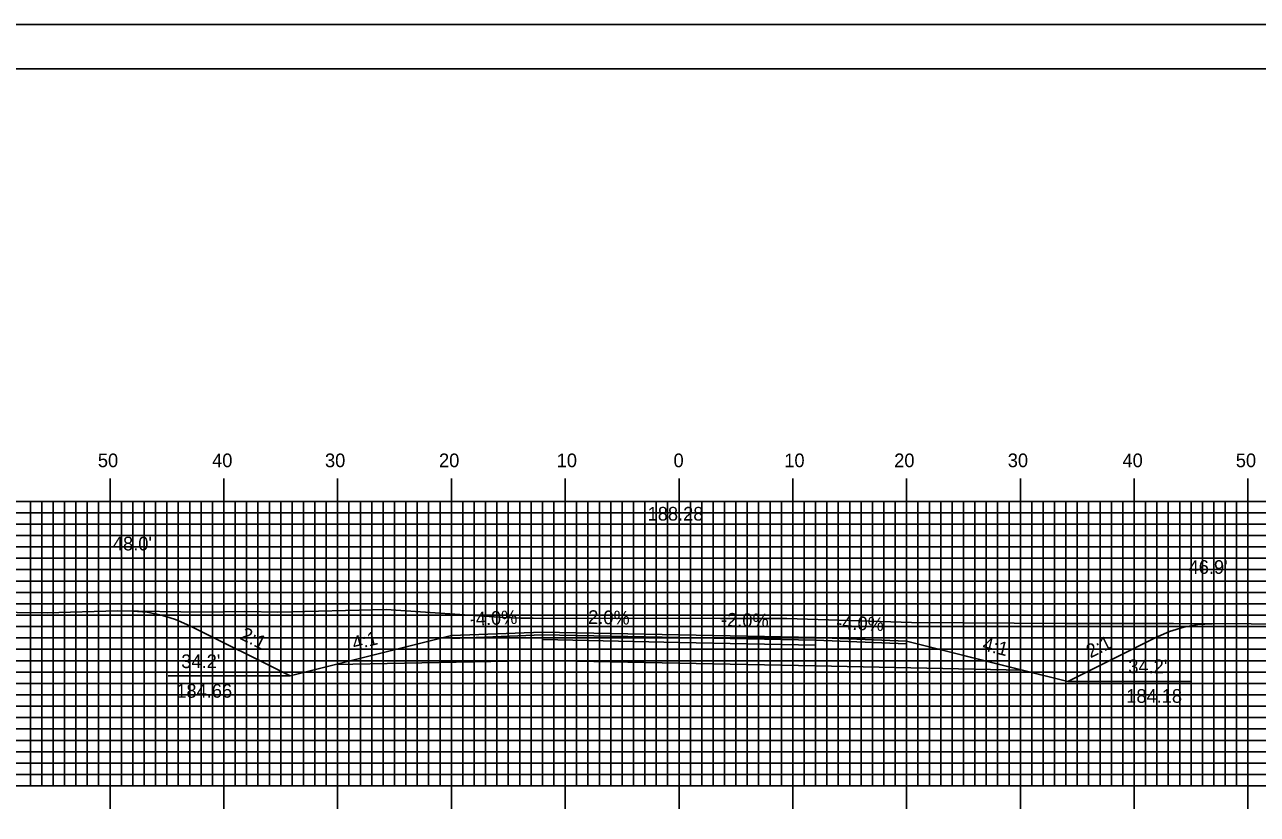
# Model space of a CAD drawing. Extents: x 1797994 to 1798337, y 442591 to 442811.
# Drawn here: x 1798102.5 to 1798210.8, y 442741.2 to 442810.5 of the extents above; entities that cross this region are included whole.
import ezdxf

# ---------------------------------------------------------------- set-up
doc = ezdxf.new("R2010")
doc.units = 0
for name, color, linetype in [('ANNOTATION', 7, 'Continuous'), ('BORDER', 7, 'Continuous'), ('D_Roadway_Centerline', 7, 'Continuous'), ('D_Roadway_Centerline_Text', 7, 'Continuous'), ('D_Roadway_Edge_Shoulder', 7, 'Continuous'), ('D_Roadway_Edge_TW', 7, 'Continuous'), ('D_Roadway_Pavement', 7, 'Continuous'), ('D_Roadway_SlopeLines', 7, 'Continuous'), ('D_Roadway_SubGrade', 7, 'Continuous'), ('D_Text_Standard', 7, 'Continuous'), ('H_V ANNOTATION', 7, 'Continuous'), ('MAJOR', 7, 'Continuous'), ('MINOR', 7, 'Continuous'), ('PDRAIN', 7, 'Continuous'), ('PLOT BOUNDARY', 7, 'Continuous'), ('S_Roadway_Centerline', 7, 'Continuous')]:
    doc.layers.add(name, color=color, linetype=linetype)

msp = doc.modelspace()

# ---------------------------------------------------------------- linework, layer by layer
at = {"layer": 'BORDER'}
msp.add_lwpolyline([(1798010.36, 442596.67), (1798330.36, 442596.67), (1798330.36, 442806.67), (1798010.36, 442806.67)], close=True, dxfattribs=at)
at = {"layer": 'D_Roadway_Centerline'}
msp.add_lwpolyline([(1798111.97, 442759.03), (1798113.22, 442758.93), (1798114.47, 442758.68), (1798115.72, 442758.28), (1798116.97, 442757.73), (1798125.78, 442753.33), (1798129.78, 442754.33), (1798139.96, 442756.87), (1798147.96, 442757.19), (1798159.96, 442756.95), (1798171.96, 442756.71), (1798179.96, 442756.39), (1798190.13, 442753.85), (1798194.13, 442752.85), (1798201.81, 442756.69), (1798203.06, 442757.23), (1798204.31, 442757.62), (1798205.56, 442757.85), (1798206.81, 442757.92)], dxfattribs=at)
at = {"layer": 'D_Roadway_Edge_Shoulder'}
for points in [[(1798147.96, 442757.19), (1798139.96, 442756.87), (1798139.96, 442756.62), (1798147.96, 442756.94)], [(1798171.96, 442756.71), (1798179.96, 442756.39), (1798179.96, 442756.14), (1798171.96, 442756.46)]]:
    msp.add_lwpolyline(points, close=True, dxfattribs=at)
at = {"layer": 'D_Roadway_Edge_TW'}
msp.add_lwpolyline([(1798147.96, 442756.94), (1798147.96, 442757.19), (1798159.96, 442756.95), (1798171.96, 442756.71), (1798171.96, 442756.46), (1798159.96, 442756.7)], close=True, dxfattribs=at)
at = {"layer": 'D_Roadway_Pavement'}
msp.add_lwpolyline([(1798147.96, 442756.52), (1798147.96, 442756.94), (1798159.96, 442756.7), (1798171.96, 442756.46), (1798171.96, 442756.04), (1798159.96, 442756.28)], close=True, dxfattribs=at)
at = {"layer": 'D_Roadway_SlopeLines'}
for points in [[(1798125.78, 442753.33), (1798116.97, 442757.73), (1798115.72, 442758.28), (1798114.47, 442758.68), (1798113.22, 442758.93), (1798111.97, 442759.03)], [(1798194.13, 442752.85), (1798201.81, 442756.69), (1798203.06, 442757.23), (1798204.31, 442757.62), (1798205.56, 442757.85), (1798206.81, 442757.92)], [(1798139.96, 442756.87), (1798125.78, 442753.33)], [(1798179.96, 442756.39), (1798194.13, 442752.85)]]:
    msp.add_lwpolyline(points, dxfattribs=at)
at = {"layer": 'D_Roadway_SubGrade'}
msp.add_lwpolyline([(1798147.96, 442754.69), (1798129.78, 442754.33), (1798139.96, 442756.87), (1798139.96, 442756.62), (1798147.96, 442756.94), (1798159.96, 442756.7), (1798171.96, 442756.46), (1798179.96, 442756.14), (1798179.96, 442756.39), (1798190.13, 442753.85), (1798171.96, 442754.21), (1798159.96, 442754.45)], close=True, dxfattribs=at)
at = {"layer": 'MAJOR'}
for p, q in [((1798109.96, 442770.67), (1798109.96, 442768.67)), ((1798119.96, 442770.67), (1798119.96, 442768.67)), ((1798129.96, 442770.67), (1798129.96, 442768.67)), ((1798139.96, 442770.67), (1798139.96, 442768.67)), ((1798149.96, 442770.67), (1798149.96, 442768.67)), ((1798159.96, 442770.67), (1798159.96, 442768.67)), ((1798169.96, 442770.67), (1798169.96, 442768.67)), ((1798179.96, 442770.67), (1798179.96, 442768.67)), ((1798189.96, 442770.67), (1798189.96, 442768.67)), ((1798199.96, 442770.67), (1798199.96, 442768.67)), ((1798209.96, 442770.67), (1798209.96, 442768.67)), ((1798019.96, 442768.67), (1798299.96, 442768.67)), ((1798019.96, 442768.67), (1798299.96, 442768.67)), ((1798109.96, 442743.67), (1798109.96, 442768.67)), ((1798119.96, 442743.67), (1798119.96, 442768.67)), ((1798129.96, 442743.67), (1798129.96, 442768.67)), ((1798139.96, 442743.67), (1798139.96, 442768.67)), ((1798149.96, 442743.67), (1798149.96, 442768.67)), ((1798159.96, 442743.67), (1798159.96, 442768.67)), ((1798169.96, 442743.67), (1798169.96, 442768.67)), ((1798179.96, 442743.67), (1798179.96, 442768.67)), ((1798189.96, 442743.67), (1798189.96, 442768.67)), ((1798199.96, 442743.67), (1798199.96, 442768.67)), ((1798209.96, 442743.67), (1798209.96, 442768.67)), ((1798019.96, 442763.67), (1798299.96, 442763.67)), ((1798019.96, 442758.67), (1798299.96, 442758.67)), ((1798019.96, 442753.67), (1798299.96, 442753.67)), ((1798019.96, 442748.67), (1798299.96, 442748.67)), ((1798019.96, 442743.67), (1798299.96, 442743.67)), ((1798019.96, 442743.67), (1798299.96, 442743.67)), ((1798109.96, 442741.66), (1798109.96, 442743.67)), ((1798119.96, 442741.66), (1798119.96, 442743.67)), ((1798129.96, 442741.66), (1798129.96, 442743.67)), ((1798139.96, 442741.66), (1798139.96, 442743.67)), ((1798149.96, 442741.66), (1798149.96, 442743.67)), ((1798159.96, 442741.66), (1798159.96, 442743.67)), ((1798169.96, 442741.66), (1798169.96, 442743.67)), ((1798179.96, 442741.66), (1798179.96, 442743.67)), ((1798189.96, 442741.66), (1798189.96, 442743.67)), ((1798199.96, 442741.66), (1798199.96, 442743.67)), ((1798209.96, 442741.66), (1798209.96, 442743.67))]:
    msp.add_line(p, q, dxfattribs=at)
at = {"layer": 'MINOR'}
for p, q in [((1798102.96, 442743.67), (1798102.96, 442768.67)), ((1798103.96, 442743.67), (1798103.96, 442768.67)), ((1798104.96, 442743.67), (1798104.96, 442768.67)), ((1798105.96, 442743.67), (1798105.96, 442768.67)), ((1798106.96, 442743.67), (1798106.96, 442768.67)), ((1798107.96, 442743.67), (1798107.96, 442768.67)), ((1798108.96, 442743.67), (1798108.96, 442768.67)), ((1798110.96, 442743.67), (1798110.96, 442768.67)), ((1798111.96, 442743.67), (1798111.96, 442768.67)), ((1798112.96, 442743.67), (1798112.96, 442768.67)), ((1798113.96, 442743.67), (1798113.96, 442768.67)), ((1798114.96, 442743.67), (1798114.96, 442768.67)), ((1798115.96, 442743.67), (1798115.96, 442768.67)), ((1798116.96, 442743.67), (1798116.96, 442768.67)), ((1798117.96, 442743.67), (1798117.96, 442768.67)), ((1798118.96, 442743.67), (1798118.96, 442768.67)), ((1798120.96, 442743.67), (1798120.96, 442768.67)), ((1798121.96, 442743.67), (1798121.96, 442768.67)), ((1798122.96, 442743.67), (1798122.96, 442768.67)), ((1798123.96, 442743.67), (1798123.96, 442768.67)), ((1798124.96, 442743.67), (1798124.96, 442768.67)), ((1798125.96, 442743.67), (1798125.96, 442768.67)), ((1798126.96, 442743.67), (1798126.96, 442768.67)), ((1798127.96, 442743.67), (1798127.96, 442768.67)), ((1798128.96, 442743.67), (1798128.96, 442768.67)), ((1798130.96, 442743.67), (1798130.96, 442768.67)), ((1798131.96, 442743.67), (1798131.96, 442768.67)), ((1798132.96, 442743.67), (1798132.96, 442768.67)), ((1798133.96, 442743.67), (1798133.96, 442768.67)), ((1798134.96, 442743.67), (1798134.96, 442768.67)), ((1798135.96, 442743.67), (1798135.96, 442768.67)), ((1798136.96, 442743.67), (1798136.96, 442768.67)), ((1798137.96, 442743.67), (1798137.96, 442768.67)), ((1798138.96, 442743.67), (1798138.96, 442768.67)), ((1798140.96, 442743.67), (1798140.96, 442768.67)), ((1798141.96, 442743.67), (1798141.96, 442768.67)), ((1798142.96, 442743.67), (1798142.96, 442768.67)), ((1798143.96, 442743.67), (1798143.96, 442768.67)), ((1798144.96, 442743.67), (1798144.96, 442768.67)), ((1798145.96, 442743.67), (1798145.96, 442768.67)), ((1798146.96, 442743.67), (1798146.96, 442768.67)), ((1798147.96, 442743.67), (1798147.96, 442768.67)), ((1798148.96, 442743.67), (1798148.96, 442768.67)), ((1798150.96, 442743.67), (1798150.96, 442768.67)), ((1798151.96, 442743.67), (1798151.96, 442768.67)), ((1798152.96, 442743.67), (1798152.96, 442768.67)), ((1798153.96, 442743.67), (1798153.96, 442768.67)), ((1798154.96, 442743.67), (1798154.96, 442768.67)), ((1798155.96, 442743.67), (1798155.96, 442768.67)), ((1798156.96, 442743.67), (1798156.96, 442768.67)), ((1798157.96, 442743.67), (1798157.96, 442768.67)), ((1798158.96, 442743.67), (1798158.96, 442768.67)), ((1798160.96, 442743.67), (1798160.96, 442768.67)), ((1798161.96, 442743.67), (1798161.96, 442768.67)), ((1798162.96, 442743.67), (1798162.96, 442768.67)), ((1798163.96, 442743.67), (1798163.96, 442768.67)), ((1798164.96, 442743.67), (1798164.96, 442768.67)), ((1798165.96, 442743.67), (1798165.96, 442768.67)), ((1798166.96, 442743.67), (1798166.96, 442768.67)), ((1798167.96, 442743.67), (1798167.96, 442768.67)), ((1798168.96, 442743.67), (1798168.96, 442768.67)), ((1798170.96, 442743.67), (1798170.96, 442768.67)), ((1798171.96, 442743.67), (1798171.96, 442768.67)), ((1798172.96, 442743.67), (1798172.96, 442768.67)), ((1798173.96, 442743.67), (1798173.96, 442768.67)), ((1798174.96, 442743.67), (1798174.96, 442768.67)), ((1798175.96, 442743.67), (1798175.96, 442768.67)), ((1798176.96, 442743.67), (1798176.96, 442768.67)), ((1798177.96, 442743.67), (1798177.96, 442768.67)), ((1798178.96, 442743.67), (1798178.96, 442768.67)), ((1798180.96, 442743.67), (1798180.96, 442768.67)), ((1798181.96, 442743.67), (1798181.96, 442768.67)), ((1798182.96, 442743.67), (1798182.96, 442768.67)), ((1798183.96, 442743.67), (1798183.96, 442768.67)), ((1798184.96, 442743.67), (1798184.96, 442768.67)), ((1798185.96, 442743.67), (1798185.96, 442768.67)), ((1798186.96, 442743.67), (1798186.96, 442768.67)), ((1798187.96, 442743.67), (1798187.96, 442768.67)), ((1798188.96, 442743.67), (1798188.96, 442768.67)), ((1798190.96, 442743.67), (1798190.96, 442768.67)), ((1798191.96, 442743.67), (1798191.96, 442768.67)), ((1798192.96, 442743.67), (1798192.96, 442768.67)), ((1798193.96, 442743.67), (1798193.96, 442768.67)), ((1798194.96, 442743.67), (1798194.96, 442768.67)), ((1798195.96, 442743.67), (1798195.96, 442768.67)), ((1798196.96, 442743.67), (1798196.96, 442768.67)), ((1798197.96, 442743.67), (1798197.96, 442768.67)), ((1798198.96, 442743.67), (1798198.96, 442768.67)), ((1798200.96, 442743.67), (1798200.96, 442768.67)), ((1798201.96, 442743.67), (1798201.96, 442768.67)), ((1798202.96, 442743.67), (1798202.96, 442768.67)), ((1798203.96, 442743.67), (1798203.96, 442768.67)), ((1798204.96, 442743.67), (1798204.96, 442768.67)), ((1798205.96, 442743.67), (1798205.96, 442768.67)), ((1798206.96, 442743.67), (1798206.96, 442768.67)), ((1798207.96, 442743.67), (1798207.96, 442768.67)), ((1798208.96, 442743.67), (1798208.96, 442768.67)), ((1798019.96, 442767.67), (1798299.96, 442767.67)), ((1798019.96, 442766.67), (1798299.96, 442766.67)), ((1798019.96, 442765.67), (1798299.96, 442765.67)), ((1798019.96, 442764.67), (1798299.96, 442764.67)), ((1798019.96, 442762.67), (1798299.96, 442762.67)), ((1798019.96, 442761.67), (1798299.96, 442761.67)), ((1798019.96, 442760.67), (1798299.96, 442760.67)), ((1798019.96, 442759.67), (1798299.96, 442759.67)), ((1798019.96, 442757.67), (1798299.96, 442757.67)), ((1798019.96, 442756.67), (1798299.96, 442756.67)), ((1798019.96, 442755.67), (1798299.96, 442755.67)), ((1798019.96, 442754.67), (1798299.96, 442754.67)), ((1798019.96, 442752.67), (1798299.96, 442752.67)), ((1798019.96, 442751.67), (1798299.96, 442751.67)), ((1798019.96, 442750.67), (1798299.96, 442750.67)), ((1798019.96, 442749.67), (1798299.96, 442749.67)), ((1798019.96, 442747.67), (1798299.96, 442747.67)), ((1798019.96, 442746.67), (1798299.96, 442746.67)), ((1798019.96, 442745.67), (1798299.96, 442745.67)), ((1798019.96, 442744.67), (1798299.96, 442744.67))]:
    msp.add_line(p, q, dxfattribs=at)
at = {"layer": 'PDRAIN'}
for p, q in [((1798115.06, 442753.33), (1798125.78, 442753.33)), ((1798194.13, 442752.85), (1798204.9, 442752.85))]:
    msp.add_line(p, q, dxfattribs=at)
at = {"layer": 'PLOT BOUNDARY'}
msp.add_lwpolyline([(1797994.17, 442590.55), (1798334.17, 442590.55), (1798334.17, 442810.55), (1797994.17, 442810.55)], close=True, dxfattribs=at)
at = {"layer": 'S_Roadway_Centerline'}
msp.add_lwpolyline([(1798099.12, 442758.93), (1798104.44, 442758.87), (1798110.61, 442759.05), (1798118.02, 442758.92), (1798121.82, 442758.98), (1798124.72, 442758.94), (1798134.22, 442759.18), (1798144.58, 442758.47), (1798145.97, 442758.42), (1798147.15, 442758.41), (1798163.62, 442758.39), (1798168.73, 442758.39), (1798169.03, 442758.39), (1798169.45, 442758.37), (1798180.39, 442758.02), (1798193.91, 442757.93), (1798203.42, 442757.94), (1798210.23, 442757.91), (1798220.57, 442757.78)], dxfattribs=at)

# ---------------------------------------------------------------- texts
at = {"layer": 'ANNOTATION'}
for s, rotation, p in [('-4.0%', 2.2906, (1798141.59, 442757.74)), ('2.0%', 358.8542, (1798151.96, 442757.91)), ('-2.0%', 358.8542, (1798163.64, 442757.68)), ('-4.0%', 357.7094, (1798173.75, 442757.44)), ('2:1', 333.4349, (1798121.31, 442756.6)), ('4:1', 14.0362, (1798131.41, 442755.59)), ('4:1', 345.9638, (1798186.55, 442755.6)), ('2:1', 26.5651, (1798196.12, 442754.87))]:
    msp.add_text(s, height=1.2, rotation=rotation, dxfattribs=at).set_placement(p)
for s, p in [("34.2'", (1798116.22, 442754.02)), ("34.2'", (1798199.44, 442753.57)), ('184.66', (1798115.78, 442751.42)), ('184.18', (1798199.26, 442750.97))]:
    msp.add_text(s, height=1.2, dxfattribs=at).set_placement(p)
at = {"layer": 'D_Roadway_Centerline'}
for s, p in [('C', (1798159.95, 442756.95)), ('L', (1798159.96, 442756.94))]:
    msp.add_text(s, height=0.0146, dxfattribs=at).set_placement(p)
at = {"layer": 'D_Roadway_Centerline_Text'}
msp.add_text('188.28', height=1.2, dxfattribs=at).set_placement((1798157.2, 442766.98))
at = {"layer": 'D_Text_Standard'}
for s, p in [("48.0'", (1798110.21, 442764.36)), ("46.9'", (1798204.74, 442762.3))]:
    msp.add_text(s, height=1.2, dxfattribs=at).set_placement(p)
at = {"layer": 'H_V ANNOTATION'}
for s, p in [('50', (1798108.89, 442771.67)), ('40', (1798118.93, 442771.67)), ('30', (1798128.85, 442771.67)), ('20', (1798138.87, 442771.67)), ('10', (1798149.21, 442771.67)), ('0', (1798159.48, 442771.67)), ('10', (1798169.21, 442771.67)), ('20', (1798178.87, 442771.67)), ('30', (1798188.85, 442771.67)), ('40', (1798198.93, 442771.67)), ('50', (1798208.89, 442771.67))]:
    msp.add_text(s, height=1.2, dxfattribs=at).set_placement(p)

doc.saveas('drawing.dxf')
